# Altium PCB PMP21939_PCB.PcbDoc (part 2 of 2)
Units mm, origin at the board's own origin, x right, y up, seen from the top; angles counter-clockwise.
Board outline 80 x 87.63 mm, 4 copper layers (Top Layer, Signal Layer 1, Signal Layer 2, Bottom Layer), stack 1.565 mm thick; 129 components, 68 nets, 325 pads, 91 vias.
Unrouted connection lines stored in the file: 2.
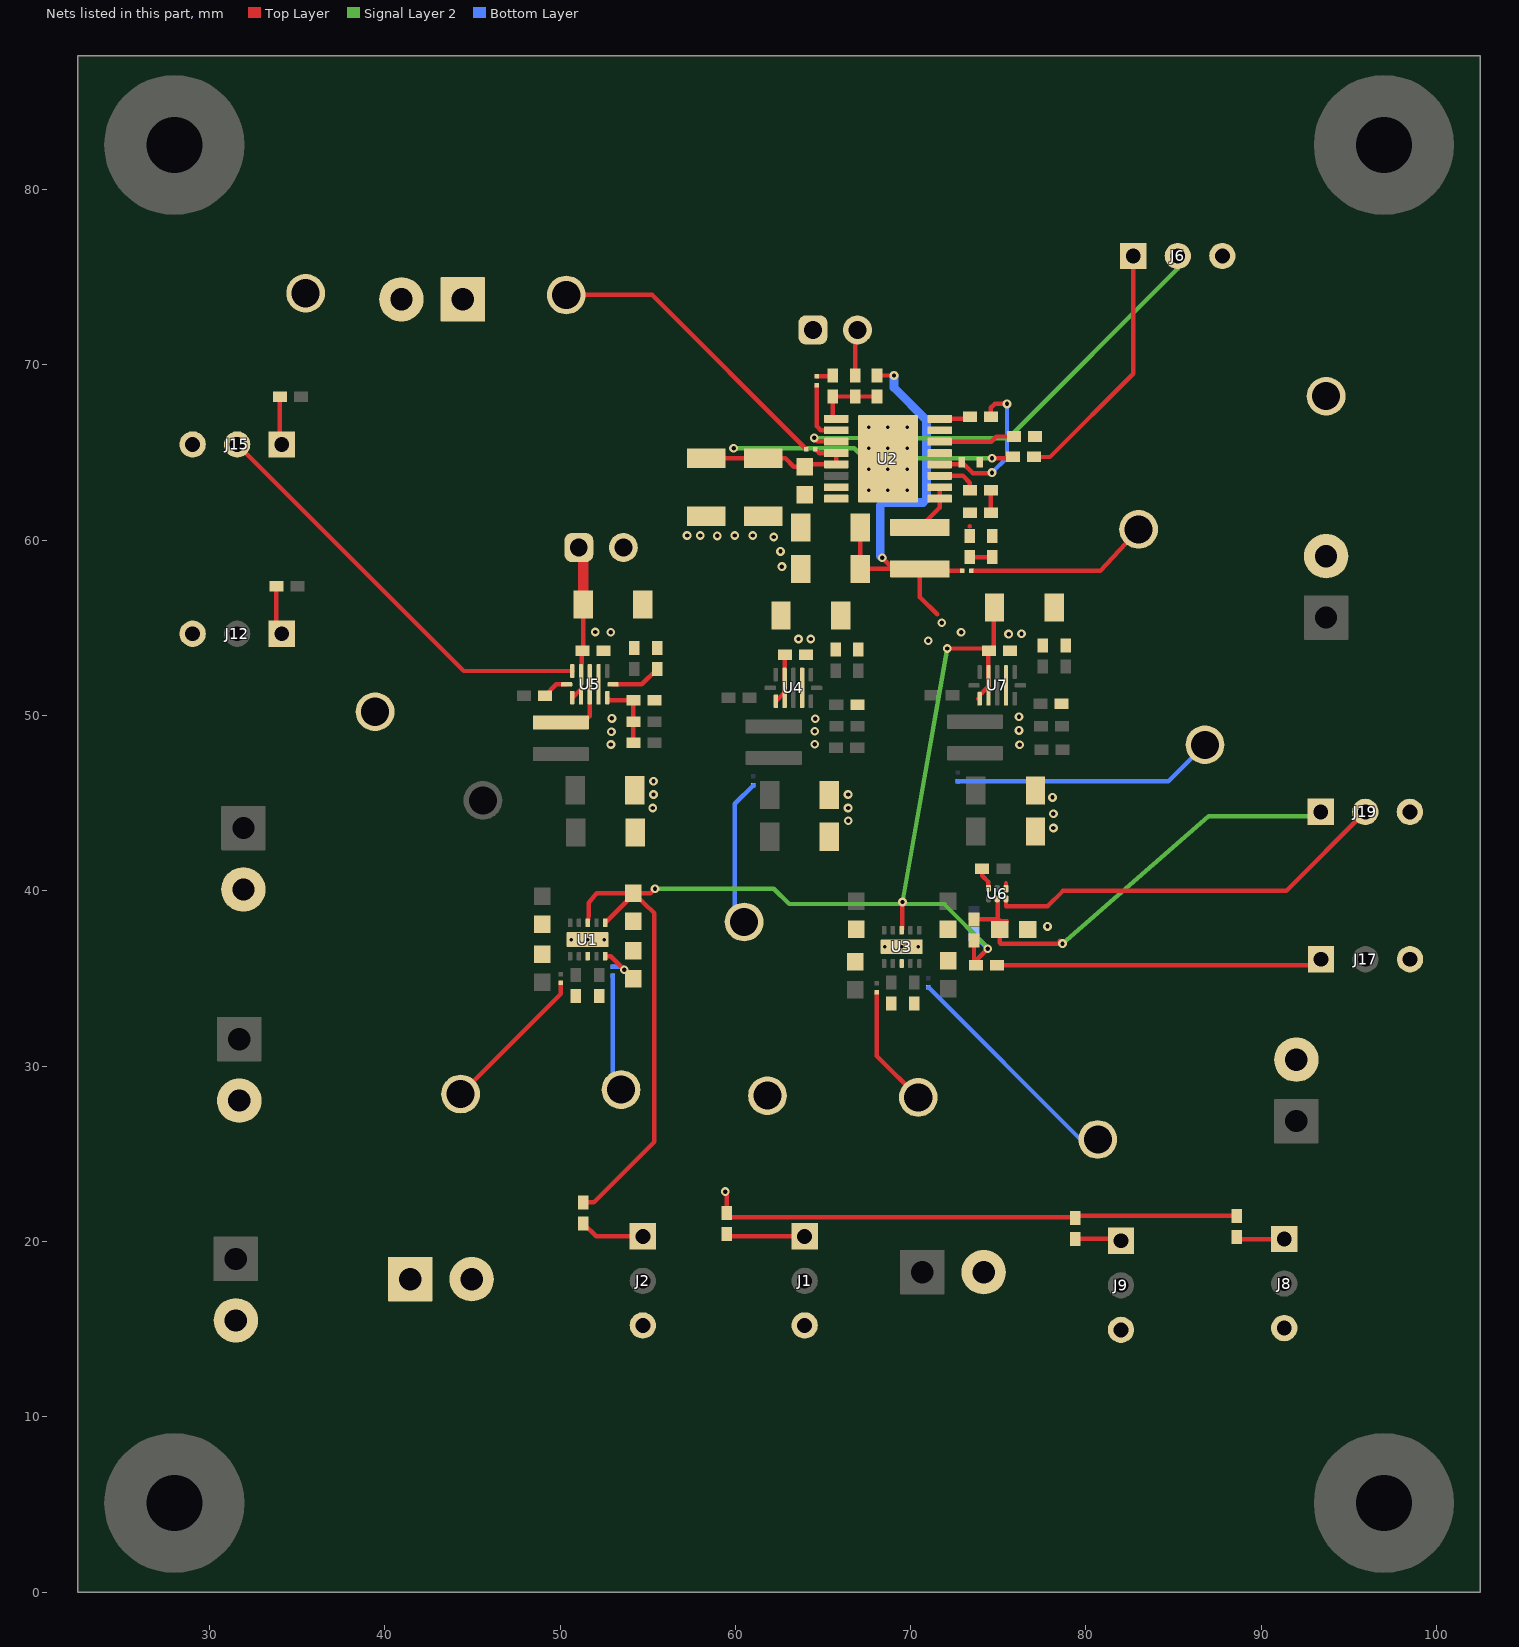
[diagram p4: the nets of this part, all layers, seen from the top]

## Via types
v1: diameter 0.5, hole 0.25, Top Layer to Bottom Layer, 72 vias
v2: diameter 0.5, hole 0.2, Top Layer to Bottom Layer, 12 vias
v3: diameter 0.5, hole 0.2, Top Layer to Bottom Layer, tented both sides, 6 vias
v4: diameter 0.5, hole 0.25, Top Layer to Bottom Layer, tented both sides, 1 vias

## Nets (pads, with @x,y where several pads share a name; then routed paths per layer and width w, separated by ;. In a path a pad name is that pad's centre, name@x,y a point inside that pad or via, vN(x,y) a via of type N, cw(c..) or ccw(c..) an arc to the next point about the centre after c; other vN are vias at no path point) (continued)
3V3_EN: J15.2 U5.8 | length 24.5
  Top Layer w0.254: J15.2@31.584,65.468 44.509,52.543 U5.8@50.699,52.543
3V3_FB: C26.2 R16.1 R17.2 U5.5 | length 4
  Top Layer w0.254: U5.5@52.699,51.021 52.843,50.877 R17.2@54.186,50.877 R16.1@54.186,49.655 C26.2@54.186,48.448
3V3_PG: R18.1 U5.9 | length 1.5
  Top Layer w0.254: R18.1@49.141,51.142 49.781,51.782 U5.9@50.374,51.782
3V3_SS: C29.1 U5.6 | length 2.9
  Top Layer w0.254: U5.6@53.024,51.782 54.669,51.782 C29.1@55.538,52.651
3V3_SW: L3.1 U5.3@51.699,51.782 | length 2.9
  Top Layer w0.254: L3.1@50.793,49.542 51.27,49.542 51.701,49.973 U5.3@51.701,51.782
GND: C1.2 C2.2 C3.2 C4.2 C5.2 C6.2 C8.2 C9.2 C10.2 C11.2 C12.2 C13.2 C14.2 C15.2 C16.2 C17.2 C18.2 C19.2 C21.2 C22.2 C23.2 C24.2 C25.2 C27.2 C28.2 C29.2 C31.2 C32.2 C33.2 C34.2 C35.2 C36.2 C37.2 C38.2 C39.1 J1.3 J2.3 J3.2 J4.2 J5.2 J6.3 J7.1 J8.3 J9.3 J10.2 J11.2 J12.3 J13.2 J15.3 J16.2 J17.3 J18.2 J19.3 NT5.1 R6.1 R12.1 R14.1 R17.1 R19.1 R24.1 R26.1 R29.2 TP5.1 TP8.1 TP10.1 TP13.1 U1.8 U1.11@51.579,37.226 U2.5 U2.7 U2.15 U2.16 U2.17@68.71,64.651 U3.8 U3.11@69.489,36.81 U4.4@63.812,51.58 U5.4@52.199,51.782 U6.1 U7.4@75.442,51.724 | length 1.2
  Top Layer w0.254: NT5.1@64.658,69.351 65.509,69.351 R6.1@65.559,69.401 ; U6.1@75.442,40.119 75.442,40.437
  other v1: 78.148,43.585 66.441,44 78.148,44.403 55.286,44.727 66.433,44.727 78.093,45.33 55.336,45.5 66.433,45.5 55.336,46.25 76.219,48.332 52.906,48.35 64.531,48.369 52.931,49.083 64.531,49.105 76.182,49.155 52.961,49.84 64.556,49.826 76.182,49.94 63.606,54.368 64.31,54.368 75.592,54.649 76.329,54.668 52.013,54.769 52.891,54.75 62.657,58.5 62.576,59.366 62.191,60.187 58.972,60.25 57.25,60.272 58,60.272 59.974,60.272 61,60.272
  other v2: 68.539,36.81 69.489,36.81 70.439,36.81 50.629,37.226 51.579,37.226 52.529,37.226 67.61,64.051 68.71,64.051 69.81,64.051 67.61,65.251 68.71,65.251 69.81,65.251
  other v3: 67.61,62.851 68.71,62.851 69.81,62.851 67.61,66.451 68.71,66.451 69.81,66.451
  other v4: 77.809,37.975
LSF_EN: J19.2 U6.6 | length 23.1
  Top Layer w0.254: U6.6@75.442,39.544 75.442,39.133 77.83,39.133 78.692,39.995 91.429,39.995 J19.2@95.941,44.509
NetC7_1: C7.1 R28.1 | length 1.3
  Top Layer w0.254: 74.579,61.904 74.582,61.901 ; C7.1@74.582,61.58 R28.1@74.582,62.851
NetC25_1: C25.1 C37.1 J14.1 U5.1 U5.2@51.199,51.782 | length 8
  Top Layer w0.254: U5.1@50.699,51.021 51.199,51.521 U5.2@51.199,51.782 51.247,51.83 51.247,53.652 C37.1@51.294,53.699 51.324,53.729 C25.1@51.324,55.526 ; J14.1@51.074,59.586 J14.1@51.324,59.337
  Top Layer w0.6: C25.1@51.324,56.424 J14.1@51.324,59.337
NetC39_2: C39.2 R27.2 | length 1.3
  Top Layer w0.254: R27.2@73.372,59.037 C39.2@74.647,59.037
NetJ1_1: J1.1 R1.1 | length 4.5
  Top Layer w0.254: R1.1@59.5,20.327 59.536,20.292 J1.1@63.958,20.292
NetJ2_1: J2.1 R2.1 | length 3.7
  Top Layer w0.254: R2.1@51.327,21.026 52.063,20.29 J2.1@54.724,20.29
NetJ6_1: J6.1 R4.1 | length 14.4
  Top Layer w0.254: R4.1@76.981,64.75 77.949,64.75 82.703,69.504 J6.1@82.703,76.219
NetJ7_2: J7.2 R7.1 | length 2.7
  Top Layer w0.254: R7.1@66.834,69.401 66.834,71.868 J7.2@66.966,72
NetJ8_1: J8.1 R8.1 | length 2.9
  Top Layer w0.254: R8.1@88.5,20.255 88.618,20.137 J8.1@91.316,20.137
NetJ9_1: J9.1 R9.1 | length 2.6
  Top Layer w0.254: R9.1@79.407,20.15 81.89,20.15 J9.1@82,20.04
NetJ12_1: J12.1 R10.1 | length 2.8
  Top Layer w0.254: R10.1@33.825,57.371 33.825,54.968 J12.1@34.124,54.668
NetJ15_1: J15.1 R15.1 | length 2.8
  Top Layer w0.254: R15.1@34.02,68.201 34.02,65.572 J15.1@34.124,65.468
NetJ17_1: J17.1 R21.1 | length 18.4
  Top Layer w0.254: R21.1@74.942,35.755 92.87,35.755 J17.1@93.17,36.055
NetNT1_2: NT1.2 TP1.1 | length 7.3
  Signal Layer 2 w0.254: TP1.1@53.077,29.068 TP1.1@53.481,28.664
  Bottom Layer w0.254: NT1.2@53,35.172 53,29.145 TP1.1@53.481,28.664
NetNT2_2: NT2.2 TP2.1 | length 8.7
  Top Layer w0.254: TP2.1@44.33,28.41 50.052,34.132 NT2.2@50.052,34.746
NetNT3_1: NT3.1 TP3.1 | length 17.3
  Top Layer w0.254: TP3.1@50.355,73.994 55.261,73.994 NT3.1@64.056,65.2
NetNT4_2: NT4.2 TP4.1 | length 10.6
  Top Layer w0.254: NT4.2@73.465,58.25 80.814,58.25 TP4.1@83.005,60.624
NetNT6_2: NT6.2 TP6.1 | length 13.3
  Bottom Layer w0.254: NT6.2@71.016,34.496 79.695,25.817 TP6.1@80.678,25.817
NetNT7_2: NT7.2 TP7.1 | length 7
  Top Layer w0.254: NT7.2@68.076,34.222 68.076,30.579 TP7.1@70.436,28.219
NetNT9_2: NT9.2 TP9.1 | length 9.9
  Top Layer w0.254: TP9.1@60.01,38.717 TP9.1@60.501,38.226 TP9.1@61.036,38.761
  Bottom Layer w0.254: TP9.1@60.501,38.226 59.974,38.753 59.974,44.964 NT9.2@61.036,46.026
NetNT12_2: NT12.2 TP12.1 | length 15
  Bottom Layer w0.254: NT12.2@72.678,46.246 84.707,46.246 TP12.1@86.794,48.332
NetR5_1: R5.1 U2.8 | length 1.8
  Top Layer w0.254: U2.8@71.66,66.926 73.269,66.926 R5.1@73.379,67.036
NetR29_1: R29.1 U2.6 | length 4.4
  Top Layer w0.254: U2.6@71.66,65.626 74.598,65.626 74.892,65.92 R29.1@75.892,65.92
NetR31_1: R31.1 U6.3 | length 1.3
  Top Layer w0.254: R31.1@74.086,41.25 74.086,40.864 74.442,40.508 U6.3@74.442,40.144
SGND: NT5.2 U2.10 | length 3.5
  Top Layer w0.254: NT5.2@64.658,68.843 64.658,66.501 64.882,66.276 U2.10@65.76,66.276
VBAT: C8.1 C9.1 C10.1 J5.1 NT3.2 R4.2 U2.12 U2.13 | length 26
  Top Layer w0.254: C8.1@58.338,64.676 C9.1@61.588,64.676 62.862,64.676 63.338,64.2 C10.1@63.965,64.2 ; C10.1@64.027,64.326 U2.13@65.76,64.326 U2.12@65.76,64.976 64.788,64.976 NT3.2@64.564,65.2 ; v1@74.644,64.704 v1(74.644,64.676) 75.949,64.676 R4.2@76.091,64.818
  Signal Layer 2 w0.254: v1(59.901,65.251) 66.794,65.251 67.371,64.674 74.642,64.674 v1(74.644,64.676)
VREF_B: C34.1 J19.1 R20.1 U6.5 | length 25.3
  Top Layer w0.254: R20.1@73.617,38.376 74.999,38.376 ; U6.5@74.942,39.544 74.965,39.521 74.965,38.411 74.999,38.376 ; 75.019,38.271 75.5,38.271 ; C34.1@75.079,37.796 75.079,37.041 75.128,36.992 v1(78.667,36.992) v1@78.51,37.149 ; 75.079,38.296 74.999,38.376
  Signal Layer 2 w0.254: v1(78.667,36.992) 87,44.25 93.142,44.25 J19.1@93.401,44.509
Vsys: C1.1 C11.1 C12.1 C23.1 C33.1 C36.1 C38.1 J14.2 L1.2 NT4.1 R1.2 R2.2 R3.2 R8.2 R9.2 R20.2 R21.2 R30.2 U1.1 U1.3 U3.3 U4.1 U4.2@62.812,51.58 U7.1 U7.2@74.442,51.724 | length 136.4
  Top Layer w0.254: R2.2@51.327,22.226 51.927,22.226 55.386,25.685 55.386,38.717 C1.1@54.186,39.874 ; U1.3@51.579,38.176 51.579,38.318 51.627,38.366 51.627,38.532 51.639,38.544 51.639,39.323 52.103,39.874 C1.1@54.186,39.874 ; U1.1@52.579,38.176 C1.1@54.186,39.783 ; J14.2@53.594,59.566 J14.2@53.614,59.586 ; v1(55.421,40.122) 55.172,39.874 C1.1@54.186,39.874 ; v1(59.426,22.845) 59.5,22.771 R1.2@59.5,21.626 ; R1.2@59.5,21.527 59.659,21.369 79.407,21.369 R9.2@79.407,21.35 79.512,21.455 R8.2@88.618,21.455 ; U4.1@62.312,50.819 62.812,51.319 U4.2@62.812,51.58 62.812,53.498 C38.1@62.84,53.526 ; C12.1@67.132,60.719 C11.1@67.132,58.366 L1.2@69.012,58.366 ; R3.2@68.084,69.401 v1(69.052,69.401) ; v1(68.378,59) L1.2@69.012,58.366 ; U3.3@69.489,37.76 69.535,37.806 69.535,39.366 v1(69.536,39.367) ; 71.513,55.776 70.528,56.761 L1.2@70.528,58.366 ; v1(72.086,53.826) 74.339,53.826 C36.1@74.467,53.699 ; NT4.1@72.957,58.25 70.645,58.25 L1.2@70.528,58.366 ; R20.2@73.617,37.176 73.617,35.88 R21.2@73.742,35.755 73.742,36.047 v1(74.4,36.705) ; U7.1@73.865,50.963 U7.1@73.942,50.963 73.942,51.272 74.048,51.272 74.442,51.665 U7.2@74.442,51.724 74.442,53.674 C36.1@74.467,53.699 ; C33.1@74.748,55.776 74.748,53.98 C36.1@74.467,53.699 ; L1.2@69.012,58.366 L1.2@70.528,58.366
  Signal Layer 2 w0.254: v1(55.421,40.122) 55.425,40.127 62.195,40.127 63.07,39.251 v1@69.42,39.251 ; v1(72.086,53.826) v1(69.536,39.367) v1@69.42,39.251 ; v1@74.427,36.732 71.908,39.251 v1@69.42,39.251
  Bottom Layer w0.254: R30.2@73.617,37.527 73.617,37.488 v1(74.4,36.705)
  Bottom Layer w0.5: v1(68.378,59) 68.274,59.104 68.274,61.983 68.442,62.151 70.71,62.151 70.91,62.351 70.91,66.857 69.052,68.715 v1(69.052,69.401)
  other v1: 71.011,54.267 72.882,54.755 71.772,55.302
Vsys_CBOOT: R28.2 U2.3 | length 2.5
  Top Layer w0.254: U2.3@71.758,63.578 U2.3@71.66,63.676 72.986,63.676 73.382,63.28 R28.2@73.382,62.851
Vsys_CH1: C3.1 J3.1 NT1.1 U1.10 | length 2.9
  Top Layer w0.254: U1.10@52.579,36.276 52.89,36.276 v1(53.666,35.5) C3.1@54.186,34.98
  Bottom Layer w0.254: NT1.1@53,35.68 53.486,35.68 v1(53.666,35.5)
Vsys_EN: J6.2 U2.11 | length 26.8
  Top Layer w0.254: v1(64.5,65.842) 64.688,65.654 65.76,65.654 U2.11@65.76,65.626
  Signal Layer 2 w0.254: v1(64.5,65.842) 67.417,65.828 75.571,65.828 85.243,75.5 J6.2@85.243,76.219
Vsys_FB: R3.1 R6.2 R7.2 U2.9 | length 3.9
  Top Layer w0.254: U2.9@65.76,66.926 65.559,67.127 R6.2@65.559,68.201 R7.2@66.834,68.201 R3.1@68.084,68.201
Vsys_SW: C7.2 L1.1 R27.1 U2.1 U2.2 | length 2.8
  Top Layer w0.254: L1.1@70.528,60.736 70.578,60.786 71.66,61.868 U2.1@71.66,62.376 U2.2@71.66,63.026 ; 73.369,60.786 73.382,60.799
Vsys_VCC: C13.1 R5.2 U2.4 | length 9.1
  Top Layer w0.254: U2.4@71.66,64.326 72.8,64.326 C13.1@72.924,64.45 73.556,63.818 74.603,63.818 v1(74.647,63.862) ; R5.2@74.579,67.036 74.579,67.557 74.803,67.78 v1(75.5,67.78)
  Bottom Layer w0.254: v1(74.647,63.862) 75.5,64.715 v1(75.5,67.78)
pads on no net: H1.1 H2.1 H3.1 H4.1 LBL1.0 U1.11@50.939,37.226 U1.11@52.219,37.226 U2.14 U2.17@68.71,64.651 U3.11@68.849,36.81 U3.11@70.129,36.81 U4.2@62.812,50.955 U4.2@62.812,52.205 U4.3@63.312,50.955 U4.3@63.312,52.205 U4.4@63.812,50.955 U4.4@63.812,52.205 U5.2@51.199,51.157 U5.2@51.199,52.407 U5.3@51.699,51.157 U5.3@51.699,52.407 U5.4@52.199,51.157 U5.4@52.199,52.407 U7.2@74.442,51.099 U7.2@74.442,52.349 U7.3@74.942,51.099 U7.3@74.942,52.349 U7.4@75.442,51.099 U7.4@75.442,52.349

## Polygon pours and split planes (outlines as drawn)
GND on Top Layer "TOP_LAYER_GND_P146" (solid, remove dead copper, pour order 146): 22.75,87.63 22.879,87.5 102.5,87.5 102.5,0 22.75,0
1V8_Buck on Top Layer "TOP_LAYER_1V8_BUCK_P110" (solid, remove dead copper, pour order 110): 66.362,49.938 67.612,49.938 67.612,47.004 66.355,46.999
3V3_Buck on Top Layer "TOP_LAYER_3V3_BUCK_P108" (solid, remove dead copper, pour order 108): 54.786,50.205 56.036,50.205 56.036,47.25 54.74,47.25
Vsys on Top Layer "TOP_LAYER_VSYS_P102" (solid, remove dead copper, pour order 102): 67.563,70.02 67.534,69.991 67.534,67.551 67.434,67.451 66.5,67.451 66.5,57.416 52.387,61.266 52.931,57.423 61.75,52.953 62.477,52.953 62.5,52.976 62.5,51.393 61.639,51.393 61.451,51.205 61.451,50.471 63.037,50.471 63.067,50.502 63,50.569 63,52.976 63.5,52.976 63.44,53.036 63.44,56.705 63.426,56.719 63.467,56.761 70.528,56.761 70.528,53.233 70.583,53.178 74.14,53.178 74.14,52.026 74.242,51.924 73.818,51.5 73.036,51.5 73.036,50.623 73.086,50.674 74.75,50.674 74.75,53.149 75.067,53.149 75.067,54.746 75.147,54.827 75.198,54.776 75.548,54.776 75.548,57 72.621,57 72.621,59.494 72.678,59.551 72.479,59.75 68.378,59.75 68.378,61.701 68.578,61.901 70.75,61.901 70.75,69.933 70.869,70.051
1V1_SW on Top Layer "TOP_LAYER_1V1_SW_P092" (solid, remove dead copper, pour order 92): 72,50.327 72,49 75.417,49 75.31,50.223 75.206,50.327 75.197,50.317 75.197,53 74.717,53 74.75,52.967 74.75,50.327
1V8_SW on Top Layer "TOP_LAYER_1V8_SW_P090" (solid, remove dead copper, pour order 90): 60.5,50.157 60.46,50.117 60.46,48.846 63.838,48.846 63.893,48.791 64.016,48.914 63.741,49.915 63.5,50.157 63.5,52.849 63.086,52.849 63,52.763 63,50.157
3V3_SW on Top Layer "TOP_LAYER_3V3_SW_P088" (solid, remove dead copper, pour order 88): 48.31,50.317 48.31,49.077 52.045,49.228 51.835,49.018 52,53.099 51.5,53.099 51.5,50.317
Vsys_CH1 on Top Layer "TOP_LAYER_VSYS_CH1_P080" (solid, remove dead copper, pour order 80): 52.579,36.276 39.709,23.406 39.709,13.813 43.25,13.813 43.25,20.511 43.209,20.552 54.661,32.003 54.661,35.78
1V1_CH1 on Top Layer "TOP_LAYER_1V1_CH1_P076" (solid, remove dead copper, pour order 76): 96.046,24.91 96.046,28.615 87.633,28.615 87.498,28.75 81.491,30 71.149,36.069 70.519,36.069 70.519,33.228 78.838,24.91
1V8_Buck on Top Layer "TOP_LAYER_1V8_BUCK_P072" (solid, remove dead copper, pour order 72): 58.451,51.813 59.864,42.207 60.551,40.922 70.985,36.875 64.25,42.138 67.6,39.462 64.25,46.419 64.309,48.096 60.551,48.096 60.551,51.137
1V1_Buck on Top Layer "TOP_LAYER_1V1_BUCK_P058" (solid, remove dead copper, pour order 58): 69.75,51.907 70.589,51.068 70.589,37.86 71.011,37.86 71.75,38.599 71.849,38.5 72.861,38.5 73.91,39.315 75.184,39.564 75.244,40.574 75.644,40.973 75.703,46.977 75.703,48.5 75.552,48.652 71.953,48.652 71.953,51.74 71.786,51.907
1V1_Buck on Top Layer "TOP_LAYER_1V1_BUCK_P052" (solid, remove dead copper, pour order 52): 80,51.159 80,47.212 83.572,47.212 83.572,47.483 89.976,53.887 89.976,53.949 97.462,53.949 97.513,54 97.513,57.339 89.976,57.339
3V3_CH2 on Top Layer "TOP_LAYER_3V3_CH2_P048" (solid, remove dead copper, pour order 48): 27.698,19.536 27.698,17.271 27.717,17.252 32.873,17.252 49.71,34.089 49.71,35.75 48.26,35.75
3V3_Buck on Top Layer "TOP_LAYER_3V3_BUCK_P044" (solid, remove dead copper, pour order 44): 46.863,51.852 48.342,51.852 48.373,51.821 48.363,51.81 48.363,49.991 52.459,49.829 51.559,44.371 51.559,40.664 51.498,40.664 49.272,38.438 43.917,38.438 34.643,29.164 27.756,29.164 27.756,31.265 46.863,50.372
VBAT on Top Layer "TOP_LAYER_VBAT_P040" (solid, remove dead copper, pour order 40): 42.5,78.5 42.5,63.566 66.51,63.566 66.476,65.216 65.097,65.216 64.25,64.95 50.756,78.5
Vsys_SW on Top Layer "TOP_LAYER_VSYS_SW_P018" (solid, remove dead copper, pour order 18): 70.528,63.369 70.528,61.701 68.634,61.701 68.634,60.025 73.982,59.985 73.982,62.676 72.732,62.676 72.729,63.4 70.552,63.4
GND on Bottom Layer "BOTTOM_LAYER_GND_P144" (solid, remove dead copper, pour order 144): 22.5,87.63 22.815,87.315 102.435,87.315 102.435,0.065 102.25,0.25 22.75,0.25
1V8_CH2 on Bottom Layer "BOTTOM_LAYER_1V8_CH2_P082" (solid, remove dead copper, pour order 82): 66.25,36.019 68.857,14.44 72.5,14.44 72.5,32.376 68.857,36.019
GND on Signal Layer 2 "SIGNAL_LAYER_2_GND_P142" (solid, remove dead copper, pour order 142): 22.5,87.63 102.121,87.63 102.75,87.001 102.75,0.25 22.75,0.25 22.5,0
Vsys on Signal Layer 2 "SIGNAL_LAYER_2_VSYS_P104" (solid, remove dead copper, pour order 104): 70.458,55.9 68.442,51.037 68.442,40.75 53.587,40.75 53.461,40.624 53.495,40.59 53.495,39.937 51.362,39.937 51.344,39.919 51.344,37.86 52.906,37.86 53.711,38.666 53.711,39.074 54.661,39.074 55.19,38.544 55.19,26.282 51.659,22.75 50.579,22.75 50.579,21.076 50.799,20.855 89.05,20.855 89.05,22.644 76.25,35.444 76.25,36.458 76.182,36.526 74.6,36.925 74.167,37.75 73.79,38.126 73.317,38.126 73.317,55.9
1V8_Buck on Signal Layer 2 "SIGNAL_LAYER_2_1V8_BUCK_P096" (solid, remove dead copper, pour order 96): 29.78,45.335 29.78,41.835 61.727,41.835 61.762,41.871 61.762,45.269 28.148,45.269 28.129,45.25
GND on Signal Layer 1 "SIGNAL_LAYER_1_GND_P140" (solid, remove dead copper, pour order 140): 22.5,87.63 22.755,87.375 102.625,87.375 102.625,0.375 102.75,0.25 102.5,0 22.5,0

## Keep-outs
Keep-Out Layer:
  text ".Layer_Name" at 14.656,-21.806 h1.52

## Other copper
Top Layer:
  text ".Layer_Name" at 14.656,-21.806 h1.52
Bottom Layer:
  text ".Layer_Name" at 14.656,-21.806 h1.52

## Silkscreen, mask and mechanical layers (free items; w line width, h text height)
Top Overlay:
  text "SET VSYS" at 62.817,75.355 h1.52
  text "GND" at 30.255,73.744 h1.52
  text "-" at 38.06,73.5 h1.52
  text "+" at 47,73.5 h1.52
  text "GND" at 88.258,71.621 h1.52 r90
  text "GND" at 60.091,71.449 h1.52
  text "VBAT" at 83.211,71 h1.52 r90
  text "VBAT" at 48.959,70.646 h1.52
  text "INPUT POWER" at 38.06,69.646 h1.52
  text "VSYS EN" at 85.711,68.5 h1.52 r90
  text "GND" at 92.453,64.594 h1.52
  text "1V8" at 34.62,61.376 h1.52 r90
  text "GND" at 92.25,61.278 h1.52
  text "GND" at 29.508,61 h1.52 r90
  text "3V3 EN" at 32.008,59.337 h1.52 r90
  text "VSYS" at 81.255,57.419 h1.52
  text "1V1 LOAD" at 99.25,54.053 h1.52 r90
  text "+" at 93.449,52.394 h1.52
  text "GND" at 29.453,50.278 h1.52 r90
  text "1V8 EN" at 32.008,48.621 h1.52 r90
  text "1V1_Shift" at 34.425,47.104 h1.52 r90
  text "GND" at 38.008,47.104 h1.52
  text "VREF_B" at 93.738,46.489 h1.52 r90
  text "LS EN" at 96.488,46.489 h1.52 r90
  text "GND" at 98.988,46.489 h1.52 r90
  text "+" at 31.5,45.808 h1.52
  text "1V1 BUCK" at 82.442,45.25 h1.52
  text "3V3 BUCK" at 42.25,42.207 h1.52
  text "1V8 LOAD" at 36.25,38.75 h1.52 r90
  text "VSYS" at 93.357,38.093 h1.52 r90
  text "GND" at 99,37.901 h1.52 r90
  text "1V1 EN" at 96.488,37.724 h1.52 r90
  text "GND" at 30.5,36.81 h1.52
  text "1V8_BUCK" at 57.536,35.276 h1.52
  text "+" at 31.508,33.776 h1.52
  text "GND" at 90.913,32.926 h1.52
  text "3V3 LOAD" at 36,26.5 h1.52 r90
  text "VSYS_CH1" at 50.231,25.719 h1.52
  text "3V3_CH2" at 41.334,25.317 h1.52
  text "GND" at 60.584,25.219 h1.52
  text "1V8_CH2" at 67.611,25.219 h1.52
  text "GND" at 30.25,24.75 h1.52
  text "1V1_CH1 LOAD" at 98.25,23.969 h1.52 r90
  text "+" at 91.75,23.5 h1.52
  text "1V1_CH1" at 77.982,22.719 h1.52
  text "+" at 31.25,21.3 h1.52
  text "VSYS_CH1 LOAD" at 37.75,21.11 h1.52
  text "VSYS" at 93.5,19.75 h1.52
  text "VSYS" at 83.5,19.25 h1.52
  text "VSYS" at 49.75,18.75 h1.52
  text "VSYS" at 58.75,18.63 h1.52
  text "2ON_CH2" at 83.5,17 h1.52
  text "2ON_CH1" at 93.25,17 h1.52
  text "1ON_CH2" at 47.284,16.75 h1.52
  text "2ON_CH2" at 56.25,16.75 h1.52
  text "+" at 67.611,16.5 h1.52
  text "GND" at 76.267,16.5 h1.52
  text "GND" at 50.25,14.77 h1.52
  text "GND" at 59.5,14.75 h1.52
  text "GND" at 83.5,14.5 h1.52
  text "GND" at 93.094,14.5 h1.52
  text "1V8_CH2 LOAD" at 67.75,12.75 h1.52
  text "+" at 41,12.5 h1.52
  text "GND" at 43.75,12.5 h1.52
  text "GND" at 30,12 h1.52
  text "3V3_CH2 LOAD" at 35.75,12 h1.52 r90
  text "'.PRJ_Number'.PCB_Rev" at 55.994,3.937 h2.75
  text ".Layer_Name" at 14.656,-21.806 h1.52
Bottom Overlay:
  text ".Layer_Name" at 14.656,-21.806 h1.52
Top Paste:
  text ".Layer_Name" at 14.656,-21.806 h1.52
Bottom Paste:
  text ".Layer_Name" at 14.656,-21.806 h1.52
Top Solder:
  text ".Layer_Name" at 14.656,-21.806 h1.52
  text ".Layer_Name" at 14.656,-21.806 h1.52
Bottom Solder:
  text ".Layer_Name" at 14.656,-21.806 h1.52
Drill Guide:
  text ".Layer_Name" at 14.656,-21.806 h1.52
M1 Board Outline:
  lines w0.254: 22.25,0.25 22.25,87.63 ; 22.5,0 102.75,0 ; 22.5,87.63 102.75,87.5 ; 102.5,-0.13 102.5,87.5
  text ".Layer_Name" at 14.656,-21.806 h1.52
M2 Board Dimensions:
  rectangle: 0,-6.985 3.175,-3.81
  rectangle: 3.175,-10.16 12.7,-6.985
  lines w0.178: 0,-6.985 25.4,-6.985 ; 3.175,-10.16 3.175,-3.81 ; 6.35,-10.16 6.35,-3.81 ; 12.7,-10.16 12.7,-3.81 ; 19.05,-10.16 19.05,-3.81 ; 0,-10.16 25.4,-10.16 25.4,-3.81 0,-3.81 0,-10.16
  text ".Layer_Name" at 14.656,-21.806 h1.52
M3 3D STEP Top:
  text ".Layer_Name" at 14.656,-21.806 h1.52
M4 3D STEP Bottom:
  text ".Layer_Name" at 14.656,-21.806 h1.52
M5 Assembly Top:
  lines w0.254: -7.417,-23.626 160.223,-23.626 ; -7.417,-18.462 160.274,-18.462 ; -7.417,-13.297 -7.417,-28.791 94.31,-28.791 160.274,-28.791 160.274,-13.297 -7.404,-13.297 -7.404,-28.791 32.614,-28.791 ; 55.194,-28.791 55.194,-13.297 ; 87.376,-18.462 87.376,-13.297 ; 108.712,-18.462 108.712,-13.297 ; 124.511,-28.956 124.511,-23.804
  text "COMPONENTS MARKED 'DNP' SHOULD NOT BE POPULATED." at 29.299,-8.09 h1.52
  text "ASSEMBLY VARIANT:" at 29.286,-11.024 h1.52
  text ".VariantName" at 55.601,-11.024 h1.52
  text "PCB VIEWED FROM TOP SIDE" at -5.804,-16.654 h1.52
  text "BOARD #:" at 57.099,-16.654 h1.52
  text ".PRJ_Number" at 70.955,-16.654 h1.52
  text "REV:" at 92.405,-16.654 h1.52
  text ".PCB_Rev" at 99.809,-16.654 h1.52
  text "SVN REV:" at 113.69,-16.654 h1.52
  text ".VersionControl_RevNumber" at 126.543,-16.654 h1.52
  text "TID #:" at 57.099,-21.819 h1.52
  text ".TID" at 70.955,-21.819 h1.52
  text "PLOT NAME =" at -5.804,-27.034 h1.52
  text ".plot_File_Name" at 14.656,-27.034 h1.52
  text "GENERATED    :" at 57.15,-27.034 h1.52
  text ".Print_Date" at 79.235,-27.034 h1.52
  text ".Print_Time" at 97.752,-27.034 h1.52
  text "TEXAS INSTRUMENTS" at 129.87,-27.034 h1.52
M6 Assembly Bottom:
  lines w0.254: -7.429,-18.474 160.261,-18.474 ; -7.379,-23.639 160.261,-23.639 ; 28.334,-28.969 28.334,-23.817 ; 44.133,-18.474 44.133,-13.31 ; 65.468,-18.474 65.468,-13.31 ; 97.65,-28.804 97.65,-13.31 ; 120.231,-28.804 160.249,-28.804 160.249,-13.31 -7.429,-13.31 -7.429,-28.804 58.534,-28.804 160.261,-28.804 160.261,-13.31
  text "COMPONENTS MARKED 'DNP' SHOULD NOT BE POPULATED." at 154.991,-8.077 h1.52
  text ".VariantName" at 128.473,-11.024 h1.52
  text "ASSEMBLY VARIANT:" at 154.864,-11.024 h1.52
  text ".VersionControl_RevNumber" at 26.302,-16.667 h1.52
  text "SVN REV:" at 39.154,-16.667 h1.52
  text ".PCB_Rev" at 53.035,-16.667 h1.52
  text "REV:" at 60.439,-16.667 h1.52
  text ".PRJ_Number" at 81.89,-16.667 h1.52
  text "BOARD #:" at 95.745,-16.667 h1.52
  text "PCB VIEWED FROM BOTTOM SIDE" at 158.648,-16.667 h1.52
  text ".TID" at 81.89,-21.831 h1.52
  text "TID #:" at 95.745,-21.831 h1.52
  text "TEXAS INSTRUMENTS" at 22.974,-27.047 h1.52
  text ".Print_Time" at 55.093,-27.047 h1.52
  text ".Print_Date" at 73.609,-27.047 h1.52
  text "GENERATED    :" at 95.694,-27.047 h1.52
  text ".plot_File_Name" at 138.189,-27.047 h1.52
  text "PLOT NAME =" at 158.648,-27.047 h1.52
M9 Title Sheet:
  drawing of 57 lines, arcs and shapes, not listed
  text "1" at 18.792,204.127 h1.78
  text "2" at 82.182,204.127 h1.78
  text "3" at 145.411,204.127 h1.78
  text "4" at 209.08,204.127 h1.78
  text "5" at 272.555,204.127 h1.78
  text "6" at 336.182,204.127 h1.78
  text "A" at -10.579,175.095 h1.78
  text "A" at 365.341,175.095 h1.78
  text "B" at -10.579,114.643 h1.78
  text "B" at 365.341,114.643 h1.78
  text "C" at -10.579,54.318 h1.78
  text "C" at 365.341,54.318 h1.78
  text "PROJECT TITLE:" at 288.125,7.048 h1.14
  text "PMP21939 REV A" at 289.395,3.662 h1.78
  text "DESIGNED FOR:" at 288.125,-0.597 h1.14
  text ".PRJ_Customer" at 289.395,-4.153 h1.78
  text "D" at -10.579,-5.88 h1.78
  text "D" at 365.341,-5.88 h1.78
  text "FILE NAME:" at 288.125,-8.217 h1.14
  text ".PCB_File_Name_No_Path" at 289.395,-11.265 h1.78
  text "Texas Instruments (TI) and/or its licensors do not warrant the accuracy or completeness of this specification" at 161.9,-15.376 h1.14
  text "ENGINEER:" at 288.125,-15.583 h1.14
  text "LAYOUT BY:" at 326.352,-15.583 h1.14
  text "or any information contained therein. TI and/or its licensors do not warrant that this design will meet" at 160.757,-18.237 h1.14
  text ".PRJ_Engineer" at 289.395,-19.52 h1.78
  text ".PCB_Layout" at 327.635,-19.52 h1.78
  text "the specifications, will be suitable for your application or fit for any particular purpose, or will operate in" at 160.757,-21.099 h1.14
  text ".Layer_Name" at 14.656,-21.806 h1.52
  text "ALTIUM DESIGNER VERSION:" at 326.352,-23.457 h1.14
  text "an implementation. TI and/or its licensors do not warrant that the design is production worthy. You should" at 160.757,-23.961 h1.14
  text "completely validate and test your design implementation to confirm the system functionality for your application." at 161.9,-26.822 h1.14
  text ".print_Scale" at 289.395,-26.843 h1.78
  text ".Application_BuildNumber" at 327.635,-26.843 h1.78
  text "1" at 18.792,-32.093 h1.78
  text "2" at 82.182,-32.093 h1.78
  text "3" at 145.411,-32.093 h1.78
  text "4" at 209.08,-32.093 h1.78
  text "5" at 272.555,-32.093 h1.78
  text "6" at 336.182,-32.093 h1.78
M10 Fab Notes:
  drawing of 189 lines, arcs and shapes, not listed
  text "DESIGN INFORMATION" at 314.503,161.447 h1.52
  text "MIN. TRACK WIDTH:" at 298.131,158.091 h1.52
  text "8" at 325.976,158.091 h1.52
  text "MIL" at 329.907,158.091 h1.52
  text "MIN. CLEARANCE:" at 298.131,154.938 h1.52
  text "0.2" at 324.452,154.938 h1.52
  text "mm" at 329.907,154.938 h1.52
  text "MIN. VIA PAD SIZE:" at 298.131,151.785 h1.52
  text "24" at 325.214,151.785 h1.52
  text "MIL" at 329.907,151.785 h1.52
  text "0.05mm (2MIL)" at 315.784,148.486 h1.52
  text "MINIMUM ANNULAR RING" at 289.769,148.277 h1.52
  text "EXTERNAL" at 333.768,148.277 h1.52
  text "PER" at 294.849,145.48 h1.52
  text "IPC-D-275 CLASS 2 LEVEL C" at 300.437,145.48 h1.52
  text "MIL, HOLES" at 338.238,142.928 h1.52
  text "+/-" at 328.27,142.709 h1.52
  text "+/-" at 349.961,142.709 h1.52
  text "REGISTRATION TOLERANCES:" at 289.769,142.682 h1.52
  text "METAL" at 320.243,142.682 h1.52
  text "5" at 334.879,142.683 h1.52
  text "3" at 356.037,142.683 h1.52
  text "MIL" at 358.99,142.682 h1.52
  text "HOLE SIZE TOLERANCE (UNLESS OTHERWISE SPECIFIED):" at 289.769,140.185 h1.52
  text "+/-" at 349.961,140.112 h1.52
  text "3" at 356.037,140.085 h1.52
  text "MIL" at 358.99,140.085 h1.52
  text "MATERIAL:" at 287.87,136.589 h1.52
  text "FR-4 High Tg" at 312.926,133.324 h1.52
  text "X" at 309.257,133.122 h1.52
  text "FR-408" at 298.563,133.007 h1.52
  text "OTHER" at 336.358,133.007 h1.52
  text "62 MIL (1.6mm) +/-10%" at 306.694,129.374 h1.52
  text "X" at 303.643,129.312 h1.52
  text "THICKNESS:" at 289.769,129.165 h1.52
  text "OTHER" at 339.33,129.165 h1.52
  text "TOLERANCE:" at 289.769,125.652 h1.52
  text "X" at 311.314,125.652 h1.52
  text "ANSI IPC-6012 TYPE 3 CLASS 2" at 315.836,125.652 h1.52
  text "OTHER +/-" at 315.835,121.989 h1.52
  text "BOW & TWIST:" at 289.769,118.302 h1.52
  text "X" at 311.314,118.302 h1.52
  text "ANSI IPC-6012 TYPE 3 CLASS 2" at 315.836,118.302 h1.52
  text "OTHER +/-" at 315.835,114.576 h1.52
  text "DRILLING:" at 287.87,111.258 h1.52
  text "NC_DRILL FILES" at 332.599,108.586 h1.52
  text "REFERENCE:" at 289.769,108.486 h1.52
  text "X" at 306.463,108.484 h1.52
  text "AS SHOWN" at 310.984,108.486 h1.52
  text "X" at 329.348,108.486 h1.52
  text "OTHER" at 340.168,104.873 h1.52
  text "PTH COPPER THICKNESS:" at 289.761,104.783 h1.52
  text "X" at 318.697,104.783 h1.52
  text "20-30 um" at 321.948,104.783 h1.52
  text "BOARD FINISH:" at 287.87,101.034 h1.52
  text "SILKSCREEN:" at 291.812,98.237 h1.52
  text "X" at 316.14,98.237 h1.52
  text "TOP" at 319.112,98.237 h1.52
  text "X" at 329.094,98.237 h1.52
  text "BOTTOM" at 332.091,98.237 h1.52
  text "SILKSCREEN COLOR:" at 291.812,94.295 h1.52
  text "X" at 316.115,94.295 h1.52
  text "WHITE" at 319.112,94.295 h1.52
  text "OTHER" at 332.091,94.295 h1.52
  text "X" at 319.442,90.652 h1.52
  text "GREEN" at 322.439,90.652 h1.52
  text "OTHER" at 338.136,90.652 h1.52
  text "SOLDER RESIST COLOR:" at 291.812,90.477 h1.52
  text "X" at 319.442,86.734 h1.52
  text "MATTE" at 322.439,86.734 h1.52
  text "SEMI-GLOSS" at 338.125,86.717 h1.52
  text "IMMERSION GOLD (ENIG)" at 314.819,82.345 h1.52
  text "ENEPIG" at 348.793,82.162 h1.52
  text "SURFACE FINISH:" at 287.87,82.136 h1.52
  text "IMM. TIN/SILVER OR EQUIV" at 296.24,78.649 h1.52
  text "X" at 328.078,78.549 h1.52
  text "OTHER" at 332.599,78.549 h1.52
  text "ARRAY/PANEL:" at 287.87,74.602 h1.52
  text "CUT AND TRIM PER M1 BOARD OUTLINE" at 314.819,74.393 h1.52
  text "N.C. ROUTE" at 314.819,70.94 h1.52
  text "X" at 332.295,70.94 h1.52
  text "V. SCORE" at 336.816,70.94 h1.52
  text "CERTIFICATION:" at 287.87,67.66 h1.52
  text "MATERIALS AND WORKMANSHIP FOR ALL PCBS" at 306.285,67.66 h1.52
  text "TO MEET OR EXCEED THE REQUIREMENTS OF:" at 306.285,65.271 h1.52
  text "X" at 297.078,62.003 h1.52
  text "ANSI IPC-A-600F CLASS ->" at 300.329,62.003 h1.52
  text "X" at 342.188,62.003 h1.52
  text "2" at 344.982,62.003 h1.52
  text "1" at 336.981,61.965 h1.52
  text "3" at 353.973,61.965 h1.52
  text "X" at 317.702,58.252 h1.52
  text "RoHS" at 320.953,58.252 h1.52
  text "OTHER" at 337.321,58.252 h1.52
  text "PER ORDER" at 347.407,58.252 h1.52
  text "ALL BOARDS MUST MEET OR EXCEED UL94-V0 REQUIREMENTS." at 288.569,54.345 h1.52
  text "PCB MUST BEAR THE UL94V-0 UL REGISTERED MATERIAL ID NUMBER" at 288.569,51.397 h1.52
  text "ADDITIONAL REQUIREMENTS:" at 287.87,47.094 h1.52
  text "MICROSECTION:" at 289.769,44.373 h1.52
  text "YES" at 312.775,44.373 h1.52
  text "X" at 319.951,40.75 h1.52
  text "REQUIRED" at 334.657,40.707 h1.52
  text "BARE BOARD ELEC. TEST:" at 289.769,40.634 h1.52
  text "NONE" at 322.935,40.634 h1.52
  text "PER ORDER" at 349.693,40.634 h1.52
  text "XX MIL VIAS REQUIRE NON-CONDUCTIVE FILL AND PLANARIZE" at 294.04,35.428 h1.5
  text "XX MIL VIAS REQUIRE CONDUCTIVE FILL AND PLANARIZE" at 294.243,32.787 h1.52
  text "OUTER XX MIL TRACES REQUIRE 50 OHM SINGLE-ENDED IMPEDANCE" at 294.218,28.637 h1.47
  text "LAYER 2 & 3 (INNER LAYERS) XX MIL WIDE, XX MIL SPACE / TRACES REQUIRE 100 OHM DIFFERENTIAL IMPEDANCE" at 294.015,22.65 h1.52
  text ".Layer_Name" at 14.656,-21.806 h1.52
M11 Gerber Information:
  lines w0.254: -7.417,-23.626 160.223,-23.626 ; -7.417,-18.462 160.274,-18.462 ; -7.417,-13.297 -7.417,-28.791 94.31,-28.791 160.274,-28.791 160.274,-13.297 -7.404,-13.297 -7.404,-28.791 32.614,-28.791 ; 55.194,-28.791 55.194,-13.297 ; 87.376,-18.462 87.376,-13.297 ; 108.712,-18.462 108.712,-13.297 ; 124.511,-28.956 124.511,-23.804
  text "ALL ARTWORK VIEWED FROM TOP SIDE" at -5.804,-16.654 h1.52
  text "BOARD #:" at 57.099,-16.654 h1.52
  text ".PRJ_Number" at 70.955,-16.654 h1.52
  text "REV:" at 92.405,-16.654 h1.52
  text ".PCB_Rev" at 99.809,-16.654 h1.52
  text "SVN REV:" at 113.69,-16.654 h1.52
  text ".VersionControl_RevNumber" at 126.543,-16.654 h1.52
  text "LAYER NAME =" at -5.804,-21.806 h1.52
  text "TID #:" at 57.099,-21.819 h1.52
  text ".TID" at 70.955,-21.819 h1.52
  text "PLOT NAME =" at -5.804,-27.034 h1.52
  text ".plot_File_Name" at 14.656,-27.034 h1.52
  text "GENERATED    :" at 57.15,-27.034 h1.52
  text ".Print_Date" at 79.235,-27.034 h1.52
  text ".Print_Time" at 97.752,-27.034 h1.52
  text "TEXAS INSTRUMENTS" at 129.87,-27.034 h1.52
M12 Stackup:
  drawing of 295 lines, arcs and shapes, not listed
  text "Layer" at 134.965,64.731 h1.52
  text "Name" at 145.376,64.731 h1.52
  text "Material" at 169.246,64.731 h1.52
  text "Thickness" at 191.084,64.731 h1.52
  text "Constant" at 207.59,64.731 h1.52
  text "Board Layer Stack" at 222.064,64.731 h1.52
  text "1" at 134.965,61.683 h1.52
  text "Top Overlay" at 145.376,61.683 h1.52
  text "2" at 134.965,58.635 h1.52
  text "Top Solder" at 145.376,58.635 h1.52
  text "Solder Resist" at 169.246,58.635 h1.52
  text "0.40mil" at 191.084,58.635 h1.52
  text "3.5" at 207.59,58.635 h1.52
  text "3" at 134.965,55.587 h1.52
  text "Top Layer" at 145.376,55.587 h1.52
  text "Copper" at 169.246,55.587 h1.52
  text "1.40mil" at 191.084,55.587 h1.52
  text "4" at 134.965,52.539 h1.52
  text "Dielectric 2" at 145.376,52.539 h1.52
  text "8.00mil" at 191.084,52.539 h1.52
  text "4.2" at 207.59,52.539 h1.52
  text "5" at 134.965,49.491 h1.52
  text "Signal Layer 1" at 145.376,49.491 h1.52
  text "Copper" at 169.246,49.491 h1.52
  text "1.40mil" at 191.084,49.491 h1.52
  text "6" at 134.965,46.443 h1.52
  text "Dielectric1" at 145.376,46.443 h1.52
  text "FR-4" at 169.246,46.443 h1.52
  text "40.00mil" at 191.084,46.443 h1.52
  text "4.8" at 207.59,46.443 h1.52
  text "7" at 134.965,43.395 h1.52
  text "Signal Layer 2" at 145.376,43.395 h1.52
  text "Copper" at 169.246,43.395 h1.52
  text "1.40mil" at 191.084,43.395 h1.52
  text "8" at 134.965,40.347 h1.52
  text "Dielectric 3" at 145.376,40.347 h1.52
  text "8.00mil" at 191.084,40.347 h1.52
  text "4.2" at 207.59,40.347 h1.52
  text "9" at 134.965,37.299 h1.52
  text "Bottom Layer" at 145.376,37.299 h1.52
  text "Copper" at 169.246,37.299 h1.52
  text "1.40mil" at 191.084,37.299 h1.52
  text "10" at 134.965,34.251 h1.52
  text "Bottom Solder" at 145.376,34.251 h1.52
  text "Solder Resist" at 169.246,34.251 h1.52
  text "0.40mil" at 191.084,34.251 h1.52
  text "3.5" at 207.59,34.251 h1.52
  text "11" at 134.965,31.203 h1.52
  text "Bottom Overlay" at 145.376,31.203 h1.52
  text ".Layer_Name" at 14.656,-21.806 h1.52
M13 Component Bodies Top:
  text ".Layer_Name" at 14.656,-21.806 h1.52
M14 Component Bodies Bottom:
  text ".Layer_Name" at 14.656,-21.806 h1.52
M15 Courtyards Top:
  text ".Layer_Name" at 14.656,-21.806 h1.52
M16 Courtyards Bottom:
  text ".Layer_Name" at 14.656,-21.806 h1.52
Drill Drawing:
  circle w0.254: c160.876,96.356 r0.702
  lines w0.254: 160.175,98.812 160.876,99.163 161.578,98.812 161.227,99.514 161.578,100.216 160.876,99.865 160.175,100.216 160.526,99.514 160.175,98.812 ; 160.175,102.321 160.526,102.321 160.526,101.97 161.227,101.97 161.227,102.321 161.578,102.321 161.578,103.023 161.227,103.023 161.227,103.374 160.526,103.374 160.526,103.023 160.175,103.023 160.175,102.321 ; 160.175,105.128 161.578,105.128 161.578,106.531 160.175,106.531 160.175,105.128 ; 160.175,109.689 161.578,109.689 160.876,108.286 160.175,109.689 ; 160.175,111.443 160.175,111.794 160.526,112.145 160.175,112.496 160.175,112.847 160.526,112.847 160.876,112.496 161.227,112.847 161.578,112.847 161.578,112.496 161.227,112.145 161.578,111.794 161.578,111.443 161.227,111.443 160.876,111.794 160.526,111.443 160.175,111.443 ; 160.175,114.952 160.526,114.952 160.876,114.601 161.227,114.952 161.578,114.952 161.227,115.303 161.578,115.654 161.227,115.654 160.876,116.005 160.526,115.654 160.175,115.654 160.526,115.303 160.175,114.952
  lines w0.305: 158.902,94.707 240.982,94.707 ; 158.902,116.811 240.982,116.811 ; 167.484,91.55 167.484,119.969 ; 175.917,91.55 175.917,119.969 ; 192.086,91.55 192.086,119.969 ; 198.668,91.55 198.668,119.969 ; 208.197,91.55 208.197,119.969 ; 226.595,91.55 226.595,119.969 ; 158.902,91.55 240.982,91.55 240.982,119.969 158.902,119.969 158.902,91.55
  text "Symbol" at 160.797,117.759 h1.83
  text "Quantity" at 168.431,117.759 h1.83
  text "Finished Hole Size" at 176.864,117.759 h1.83
  text "Plated" at 193.033,117.759 h1.83
  text "Hole Type" at 199.615,117.759 h1.83
  text "Drill Layer Pair" at 209.144,117.759 h1.83
  text "Hole Tolerance" at 227.542,117.759 h1.83
  text "18" at 168.431,114.601 h1.52
  text "0.200mm (7.87mil)" at 176.864,114.601 h1.52
  text "PTH" at 193.033,114.601 h1.52
  text "Round" at 199.615,114.601 h1.52
  text "Top Layer - Bottom Layer" at 209.144,114.601 h1.52
  text "73" at 168.431,111.443 h1.52
  text "0.250mm (9.84mil)" at 176.864,111.443 h1.52
  text "PTH" at 193.033,111.443 h1.52
  text "Round" at 199.615,111.443 h1.52
  text "Top Layer - Bottom Layer" at 209.144,111.443 h1.52
  text "27" at 168.431,108.286 h1.52
  text "0.850mm (33.47mil)" at 176.864,108.286 h1.52
  text "PTH" at 193.033,108.286 h1.52
  text "Round" at 199.615,108.286 h1.52
  text "Top Layer - Bottom Layer" at 209.144,108.286 h1.52
  text "4" at 168.431,105.128 h1.52
  text "1.016mm (40.00mil)" at 176.864,105.128 h1.52
  text "PTH" at 193.033,105.128 h1.52
  text "Round" at 199.615,105.128 h1.52
  text "Top Layer - Bottom Layer" at 209.144,105.128 h1.52
  text "16" at 168.431,101.97 h1.52
  text "1.270mm (50.00mil)" at 176.864,101.97 h1.52
  text "PTH" at 193.033,101.97 h1.52
  text "Round" at 199.615,101.97 h1.52
  text "Top Layer - Bottom Layer" at 209.144,101.97 h1.52
  text "13" at 168.431,98.812 h1.52
  text "1.600mm (63.00mil)" at 176.864,98.812 h1.52
  text "PTH" at 193.033,98.812 h1.52
  text "Round" at 199.615,98.812 h1.52
  text "Top Layer - Bottom Layer" at 209.144,98.812 h1.52
  text "4" at 168.431,95.655 h1.52
  text "3.200mm (125.98mil)" at 176.864,95.655 h1.52
  text "PTH" at 193.033,95.655 h1.52
  text "Round" at 199.615,95.655 h1.52
  text "Top Layer - Bottom Layer" at 209.144,95.655 h1.52
  text "155 Total" at 168.431,92.497 h1.52
  text ".Layer_Name" at 14.656,-21.806 h1.52
M17 Embedded Cavity:
  text ".Layer_Name" at 14.656,-21.806 h1.52
M18 Embedded Assembly:
  text ".Layer_Name" at 14.656,-21.806 h1.52
M19 Embedded Keepout:
  text ".Layer_Name" at 14.656,-21.806 h1.52

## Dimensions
25.993,81.885 to 98.243,81.421 on Top Overlay
29.258,81.335 to 25.758,9.085 on Top Overlay
0,-10.16 to 25.4,-10.16 on M2 Board Dimensions
20.5,0.5 to 22.5,87.63 on M2 Board Dimensions
20.25,-2 to 102.5,0 on M2 Board Dimensions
